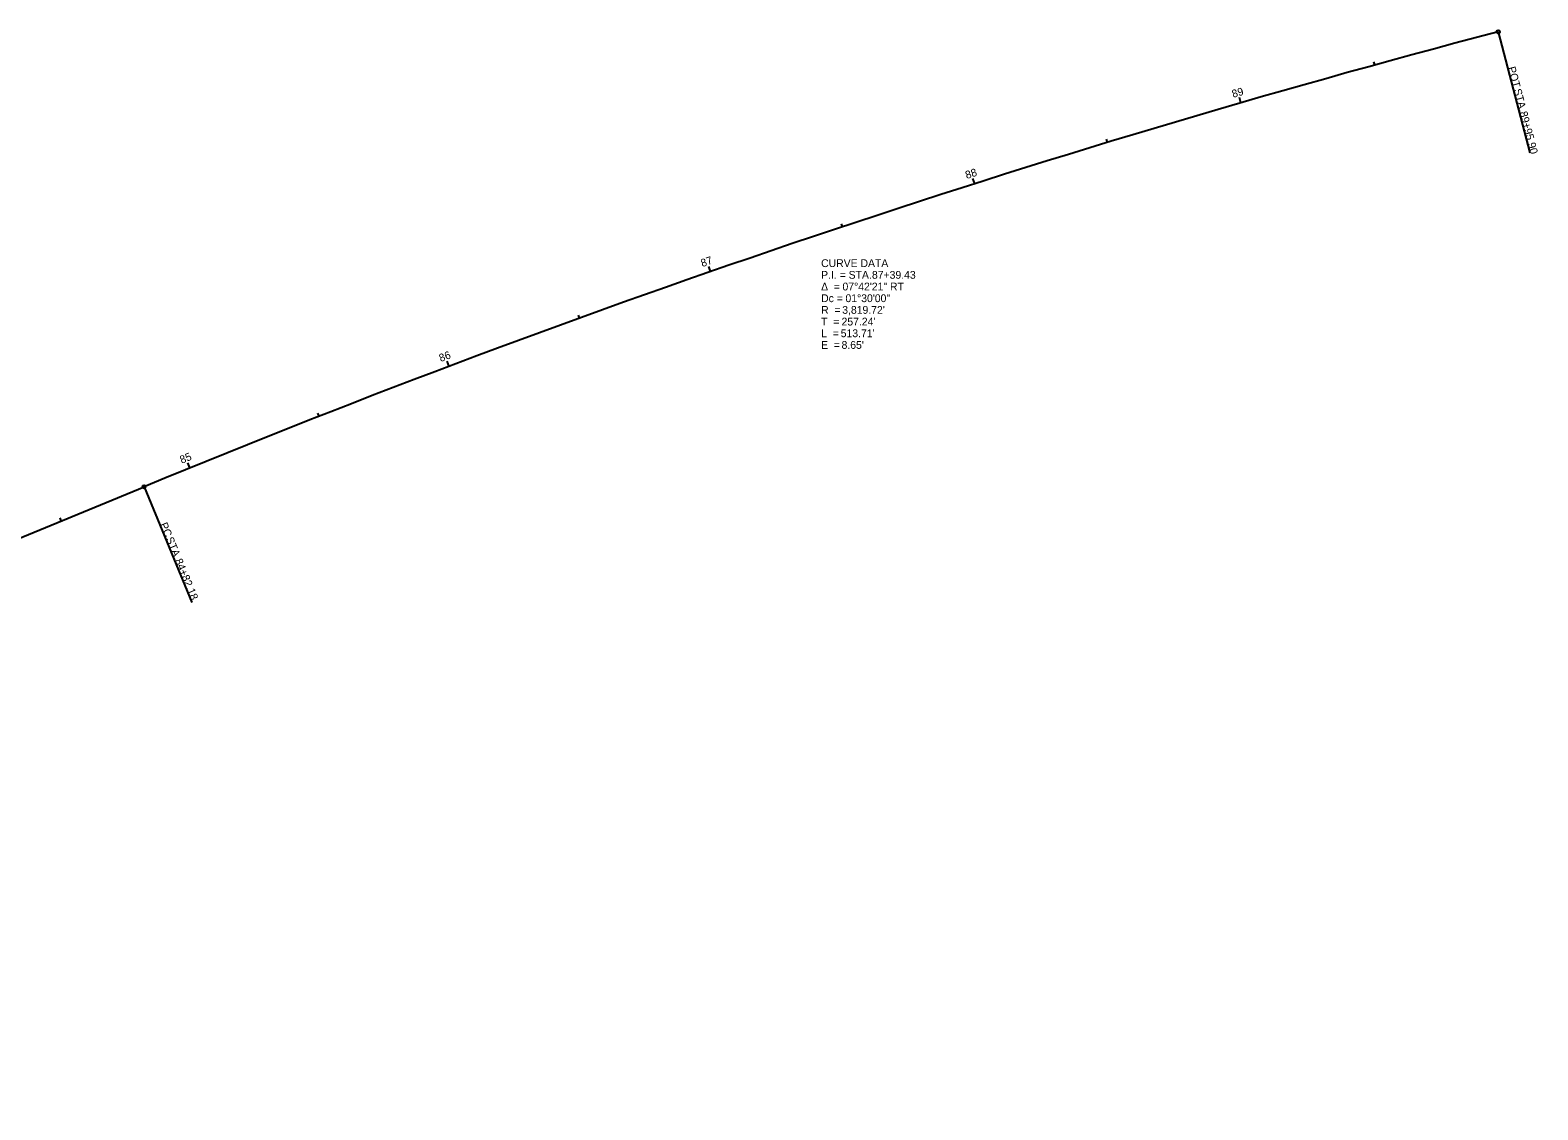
# Model space of a CAD drawing. Extents: x 2202679 to 2204820, y 634848 to 638099.
# Drawn here: x 2204278 to 2204820, y 634934 to 635322 of the extents above; entities that cross this region are included whole.
import ezdxf

# ---------------------------------------------------------------- set-up
doc = ezdxf.new("R2010")
doc.units = 0
for name, color, linetype in [('_CIVIL_CONSTRUCTION', 7, 'Continuous'), ('RW_X_CL', 7, 'Continuous'), ('RW_X_CL_100_Cardinal_Points', 7, 'Continuous'), ('SC_Scratch1', 7, 'Continuous')]:
    doc.layers.add(name, color=color, linetype=linetype)

msp = doc.modelspace()

# ---------------------------------------------------------------- linework, layer by layer
at = {"layer": 'RW_X_CL'}
for p, q in [((2204805.66, 635321.33), (2204817.09, 635277.81)), ((2204319.08, 635157.79), (2204336.25, 635116.2))]:
    msp.add_line(p, q, dxfattribs=at)
for centre in [(2204805.66, 635321.33), (2204319.08, 635157.79)]:
    msp.add_circle(centre, 0.6, dxfattribs=at)
at = {"layer": 'RW_X_CL_100_Cardinal_Points'}
for p, q in [((2204761.34, 635309.4), (2204761.02, 635310.55)), ((2204713.22, 635295.79), (2204712.67, 635297.71)), ((2204665.29, 635281.56), (2204664.94, 635282.71)), ((2204617.55, 635266.7), (2204616.94, 635268.61)), ((2204570.01, 635251.22), (2204569.63, 635252.36)), ((2204522.67, 635235.12), (2204522.02, 635237.01)), ((2204475.55, 635218.4), (2204475.14, 635219.52)), ((2204428.66, 635201.06), (2204427.95, 635202.93)), ((2204381.99, 635183.11), (2204381.55, 635184.23)), ((2204335.56, 635164.55), (2204334.81, 635166.4)), ((2204289.33, 635145.51), (2204288.87, 635146.62))]:
    msp.add_line(p, q, dxfattribs=at)
at = {"layer": 'SC_Scratch1'}
msp.add_line((2203776.43, 634933.8), (2204319.08, 635157.79), dxfattribs=at)
msp.add_line((2203776.43, 634933.8), (2204319.08, 635157.79), dxfattribs=at)
msp.add_arc((2205776.52, 631627.05), 3819.72, 104.72445, 112.43016, dxfattribs=at)
msp.add_arc((2205776.52, 631627.05), 3819.72, 104.72445, 112.43016, dxfattribs=at)

# ---------------------------------------------------------------- texts
at = {"layer": '_CIVIL_CONSTRUCTION'}
for s, p in [('CURVE DATA', (2204562.37, 635236.76)), ('P.I. = STA. ', (2204562.37, 635232.56)), ('87+39.43', (2204580.63, 635232.56)), ('Δ  = ', (2204562.37, 635228.36)), ('07°42\'21" RT', (2204570.04, 635228.36)), ('Dc = ', (2204562.37, 635224.16)), ('01°30\'00"', (2204571.11, 635224.16)), ('T  = ', (2204562.37, 635215.76)), ('R  = ', (2204562.37, 635219.96)), ("257.24'", (2204569.7, 635215.76)), ("3,819.72'", (2204569.95, 635219.96)), ('L  = ', (2204562.37, 635211.56)), ("513.71'", (2204569.41, 635211.56)), ('E  = ', (2204562.37, 635207.36)), ("8.65'", (2204569.71, 635207.36))]:
    msp.add_text(s, height=2.8, dxfattribs=at).set_placement(p)
at = {"layer": 'RW_X_CL'}
for s, rotation, p in [('POT', 284.7245, (2204809.08, 635308.46)), (' STA. ', 284.7245, (2204810.91, 635301.5)), ('89+95.90', 284.7245, (2204813.32, 635292.35)), ('PC', 292.4302, (2204324.7, 635144.28)), (' STA. ', 292.4302, (2204326.45, 635140.04)), ('84+82.18', 292.4302, (2204330.06, 635131.3))]:
    msp.add_text(s, height=2.8, rotation=rotation, dxfattribs=at).set_placement(p)
at = {"layer": 'RW_X_CL_100_Cardinal_Points'}
for s, rotation, p in [('89', 16.1629, (2204710.41, 635297.58)), ('88', 17.6629, (2204614.68, 635268.41)), ('87', 19.1629, (2204519.68, 635236.72)), ('86', 20.6629, (2204425.68, 635202.61)), ('85', 22.1629, (2204332.59, 635166.04))]:
    msp.add_text(s, height=2.8, rotation=rotation, dxfattribs=at).set_placement(p)

doc.saveas('drawing.dxf')
